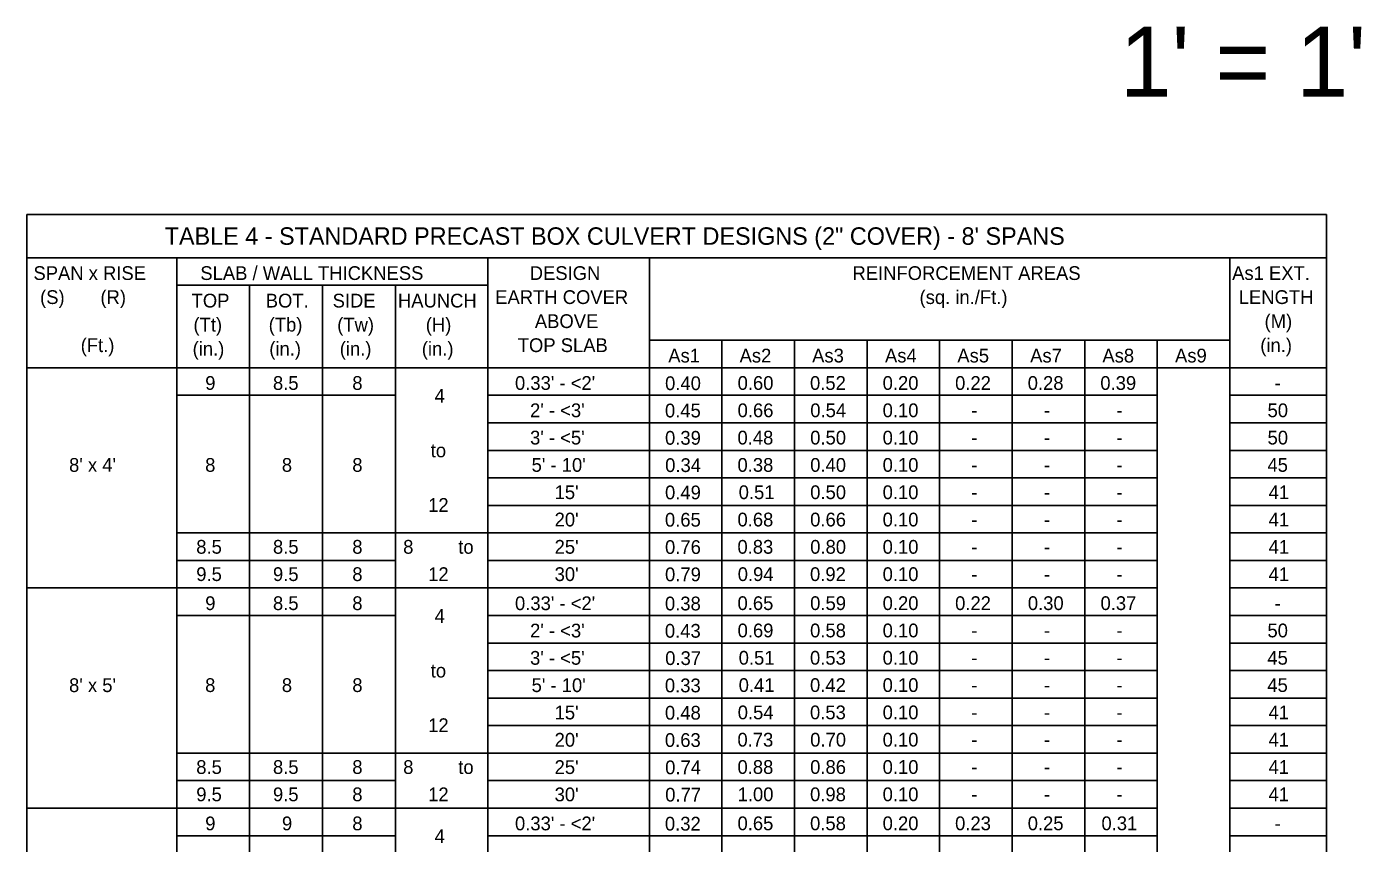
# Model space of a CAD drawing. Extents: x 10342.77 to 10344.98, y 76399.47 to 76400.59.
# Drawn here: x 10343.418 to 10344.028, y 76400.212 to 76400.586 of the extents above; entities that cross this region are included whole.
import ezdxf

# ---------------------------------------------------------------- set-up
doc = ezdxf.new("R2010")
doc.units = 0
doc.layers.add('AdhocPoint_dp', color=7, linetype='Continuous')
doc.layers.add('PlotBorder_dp', color=7, linetype='Continuous')

msp = doc.modelspace()

# ---------------------------------------------------------------- linework, layer by layer
at = {"layer": 'PlotBorder_dp'}
for p, q in [((10343.41763, 76400.49971), (10344.01237, 76400.49971)), ((10343.41763, 76400.49971), (10343.41763, 76399.92549)), ((10344.01237, 76400.49971), (10344.01237, 76399.92549)), ((10343.41763, 76400.47984), (10344.01237, 76400.47984)), ((10343.48627, 76400.47984), (10343.48627, 76399.92549)), ((10343.62871, 76400.47984), (10343.62871, 76399.92549)), ((10343.70259, 76400.47984), (10343.70259, 76399.92549)), ((10343.96818, 76400.47984), (10343.96818, 76399.92549)), ((10343.48627, 76400.46724), (10343.62871, 76400.46724)), ((10343.51963, 76400.46724), (10343.51963, 76399.92549)), ((10343.55299, 76400.46724), (10343.55299, 76399.92549)), ((10343.58635, 76400.46724), (10343.58635, 76399.92549)), ((10343.70259, 76400.44209), (10343.96818, 76400.44209)), ((10343.73579, 76400.44209), (10343.73579, 76399.92549)), ((10343.76899, 76400.44209), (10343.76899, 76399.92549)), ((10343.80219, 76400.44209), (10343.80219, 76399.92549)), ((10343.83539, 76400.44209), (10343.83539, 76399.92549)), ((10343.86859, 76400.44209), (10343.86859, 76399.92549)), ((10343.86859, 76400.44209), (10343.86859, 76399.92549)), ((10343.90178, 76400.44209), (10343.90178, 76399.92549)), ((10343.93498, 76400.44209), (10343.93498, 76399.92549)), ((10343.41763, 76400.42949), (10344.01237, 76400.42949)), ((10343.58635, 76400.41689), (10343.48627, 76400.41689)), ((10343.62871, 76400.41689), (10343.93498, 76400.41689)), ((10343.96818, 76400.41689), (10344.01237, 76400.41689)), ((10343.62871, 76400.40429), (10343.93498, 76400.40429)), ((10343.96818, 76400.40429), (10344.01237, 76400.40429)), ((10343.62871, 76400.39169), (10343.93498, 76400.39169)), ((10343.96818, 76400.39169), (10344.01237, 76400.39169)), ((10343.62871, 76400.37909), (10343.93498, 76400.37909)), ((10343.96818, 76400.37909), (10344.01237, 76400.37909)), ((10343.62871, 76400.36649), (10343.93498, 76400.36649)), ((10343.96818, 76400.36649), (10344.01237, 76400.36649)), ((10343.62871, 76400.35389), (10343.48627, 76400.35389)), ((10343.62871, 76400.35389), (10343.93498, 76400.35389)), ((10343.96818, 76400.35389), (10344.01237, 76400.35389)), ((10343.58635, 76400.34129), (10343.48627, 76400.34129)), ((10343.62871, 76400.34129), (10343.93498, 76400.34129)), ((10343.96818, 76400.34129), (10344.01237, 76400.34129)), ((10343.41763, 76400.32869), (10343.93498, 76400.32869)), ((10343.62931, 76400.32869), (10343.70148, 76400.32869)), ((10343.62931, 76400.32869), (10343.70148, 76400.32869)), ((10343.96818, 76400.32869), (10344.01237, 76400.32869)), ((10343.58635, 76400.31609), (10343.48627, 76400.31609)), ((10343.62871, 76400.31609), (10343.93498, 76400.31609)), ((10343.96818, 76400.31609), (10344.01237, 76400.31609)), ((10343.62871, 76400.30349), (10343.93498, 76400.30349)), ((10343.96818, 76400.30349), (10344.01237, 76400.30349)), ((10343.62871, 76400.29089), (10343.93498, 76400.29089)), ((10343.96818, 76400.29089), (10344.01237, 76400.29089)), ((10343.62871, 76400.27829), (10343.93498, 76400.27829)), ((10343.96818, 76400.27829), (10344.01237, 76400.27829)), ((10343.62871, 76400.26569), (10343.93498, 76400.26569)), ((10343.96818, 76400.26569), (10344.01237, 76400.26569)), ((10343.62871, 76400.25309), (10343.48627, 76400.25309)), ((10343.62871, 76400.25309), (10343.93498, 76400.25309)), ((10343.96818, 76400.25309), (10344.01237, 76400.25309)), ((10343.58635, 76400.24049), (10343.48627, 76400.24049)), ((10343.62871, 76400.24049), (10343.93498, 76400.24049)), ((10343.96818, 76400.24049), (10344.01237, 76400.24049)), ((10343.41763, 76400.22789), (10343.93498, 76400.22789)), ((10343.62931, 76400.22789), (10343.70148, 76400.22789)), ((10343.62931, 76400.22789), (10343.70148, 76400.22789)), ((10343.62931, 76400.22789), (10343.70148, 76400.22789)), ((10343.96818, 76400.22789), (10344.01237, 76400.22789)), ((10343.58635, 76400.21529), (10343.48627, 76400.21529)), ((10343.62871, 76400.21529), (10343.93498, 76400.21529)), ((10343.96818, 76400.21529), (10344.01237, 76400.21529))]:
    msp.add_line(p, q, dxfattribs=at)

# ---------------------------------------------------------------- texts
at = {"layer": 'AdhocPoint_dp'}
for s, height, p in [("1' = 1'", 0.032, (10343.91778, 76400.55363)), ('TABLE 4 - STANDARD PRECAST BOX CULVERT DESIGNS (2" COVER) - 8\' SPANS', 0.008, (10343.48078, 76400.48578)), ('SLAB / WALL THICKNESS', 0.0063, (10343.49709, 76400.46968)), ('As1', 0.0063, (10343.71121, 76400.43192)), ('As2', 0.0063, (10343.74384, 76400.43192)), ('As3', 0.0063, (10343.77704, 76400.43192)), ('As4', 0.0063, (10343.81037, 76400.43192)), ('As5', 0.0063, (10343.84347, 76400.43192)), ('As7', 0.0063, (10343.87681, 76400.43192)), ('As8', 0.0063, (10343.90985, 76400.43192)), ('As9', 0.0063, (10343.9431, 76400.43192))]:
    msp.add_text(s, height=height, dxfattribs=at).set_placement(p)
at = {"layer": 'PlotBorder_dp'}
for s, p in [('SPAN x RISE', (10343.42072, 76400.46968)), ('DESIGN', (10343.64781, 76400.46968)), ('REINFORCEMENT AREAS', (10343.79549, 76400.46968)), ('(S)       (R)', (10343.42376, 76400.45868)), ('EARTH COVER', (10343.63202, 76400.45868)), ('(sq. in./Ft.)', (10343.82619, 76400.45868)), ('TOP', (10343.49309, 76400.45708)), ('BOT.', (10343.52702, 76400.45708)), ('SIDE', (10343.55762, 76400.45708)), ('HAUNCH', (10343.58751, 76400.45708)), ('(Tt)', (10343.49394, 76400.44608)), ('(Tb)', (10343.52836, 76400.44608)), ('(Tw)', (10343.55972, 76400.44608)), ('(H)', (10343.60025, 76400.44608)), ('ABOVE', (10343.65016, 76400.44768)), ('(Ft.)', (10343.44234, 76400.43668)), ('(in.)', (10343.49355, 76400.43508)), ('(in.)', (10343.52864, 76400.43508)), ('(in.)', (10343.56088, 76400.43508)), ('(in.)', (10343.59844, 76400.43508)), ('TOP SLAB', (10343.64233, 76400.43668)), ('9', (10343.49933, 76400.41937)), ('8.5', (10343.53032, 76400.41937)), ('8', (10343.56662, 76400.41937)), ("0.33' - <2'", (10343.64107, 76400.41937)), ('0.40', (10343.70975, 76400.41927)), ('0.60', (10343.74294, 76400.41937)), ('0.52', (10343.77607, 76400.41937)), ('0.20', (10343.8093, 76400.41937)), ('0.22', (10343.84246, 76400.41937)), ('0.28', (10343.87568, 76400.41937)), ('0.39', (10343.90891, 76400.41937)), ('-', (10343.98869, 76400.41937)), ('4', (10343.60429, 76400.41352)), ("2' - <3'", (10343.64797, 76400.40687)), ('0.45', (10343.70969, 76400.40677)), ('0.66', (10343.74293, 76400.40687)), ('0.54', (10343.77619, 76400.40687)), ('0.10', (10343.8093, 76400.40687)), ('-', (10343.84986, 76400.40687)), ('-', (10343.88307, 76400.40687)), ('-', (10343.91625, 76400.40687)), ('50', (10343.98543, 76400.40687)), ("3' - <5'", (10343.64797, 76400.39437)), ('0.39', (10343.70973, 76400.39427)), ('0.48', (10343.74288, 76400.39437)), ('0.50', (10343.77615, 76400.39437)), ('0.10', (10343.8093, 76400.39437)), ('-', (10343.84986, 76400.39437)), ('-', (10343.88307, 76400.39437)), ('-', (10343.91625, 76400.39437)), ('50', (10343.98543, 76400.39437)), ('to', (10343.60251, 76400.38852)), ("8' x 4'", (10343.43702, 76400.38187)), ('8', (10343.49929, 76400.38187)), ('8', (10343.53438, 76400.38187)), ('8', (10343.56662, 76400.38187)), ("5' - 10'", (10343.64868, 76400.38187)), ('0.34', (10343.70979, 76400.38177)), ('0.38', (10343.74288, 76400.38187)), ('0.40', (10343.77615, 76400.38187)), ('0.10', (10343.8093, 76400.38187)), ('45', (10343.98538, 76400.38187)), ('-', (10343.84986, 76400.38187)), ('-', (10343.88307, 76400.38187)), ('-', (10343.91625, 76400.38187)), ("15'", (10343.6592, 76400.36937)), ('0.49', (10343.70973, 76400.36927)), ('0.51', (10343.74343, 76400.36937)), ('0.50', (10343.77615, 76400.36937)), ('0.10', (10343.8093, 76400.36937)), ('41', (10343.98592, 76400.36937)), ('12', (10343.60134, 76400.36352)), ('-', (10343.84986, 76400.36937)), ('-', (10343.88307, 76400.36937)), ('-', (10343.91625, 76400.36937)), ("20'", (10343.6592, 76400.35687)), ('0.65', (10343.70969, 76400.35677)), ('0.68', (10343.74288, 76400.35687)), ('0.66', (10343.77613, 76400.35687)), ('0.10', (10343.8093, 76400.35687)), ('41', (10343.98592, 76400.35687)), ('-', (10343.84986, 76400.35687)), ('-', (10343.88307, 76400.35687)), ('-', (10343.91625, 76400.35687)), ('8.5', (10343.49522, 76400.34437)), ('8.5', (10343.53032, 76400.34437)), ('8', (10343.56662, 76400.34437)), ('8 ', (10343.58991, 76400.34437)), ('to', (10343.61511, 76400.34437)), ("25'", (10343.6592, 76400.34437)), ('0.76', (10343.70973, 76400.34427)), ('0.83', (10343.74286, 76400.34437)), ('0.80', (10343.77615, 76400.34437)), ('0.10', (10343.8093, 76400.34437)), ('41', (10343.98592, 76400.34437)), ('-', (10343.84986, 76400.34437)), ('-', (10343.88307, 76400.34437)), ('-', (10343.91625, 76400.34437)), ('9.5', (10343.49522, 76400.33187)), ('9.5', (10343.53032, 76400.33187)), ('8', (10343.56662, 76400.33187)), ('12', (10343.60134, 76400.33187)), ("30'", (10343.6592, 76400.33187)), ('0.79', (10343.70973, 76400.33177)), ('0.94', (10343.74299, 76400.33187)), ('0.92', (10343.77607, 76400.33187)), ('0.10', (10343.8093, 76400.33187)), ('41', (10343.98592, 76400.33187)), ('-', (10343.84986, 76400.33187)), ('-', (10343.88307, 76400.33187)), ('-', (10343.91625, 76400.33187)), ('9', (10343.49933, 76400.31857)), ('8.5', (10343.53032, 76400.31857)), ('8', (10343.56662, 76400.31857)), ("0.33' - <2'", (10343.64107, 76400.31854)), ('0.38', (10343.70969, 76400.31843)), ('0.65', (10343.74289, 76400.31859)), ('0.59', (10343.77613, 76400.31859)), ('0.20', (10343.8093, 76400.31859)), ('0.22', (10343.84246, 76400.31859)), ('0.30', (10343.87574, 76400.31859)), ('0.37', (10343.90899, 76400.31859)), ('4', (10343.60429, 76400.31272)), ('-', (10343.98864, 76400.31859)), ("2' - <3'", (10343.64797, 76400.30604)), ('0.43', (10343.70966, 76400.30593)), ('0.69', (10343.74293, 76400.30609)), ('0.58', (10343.77609, 76400.30609)), ('0.10', (10343.8093, 76400.30609)), ('50', (10343.98538, 76400.30609)), ('-', (10343.84986, 76400.30609)), ('-', (10343.88307, 76400.30609)), ('-', (10343.91625, 76400.30609)), ("3' - <5'", (10343.64797, 76400.29354)), ('0.37', (10343.70981, 76400.29343)), ('0.51', (10343.74343, 76400.29359)), ('0.53', (10343.77606, 76400.29359)), ('0.10', (10343.8093, 76400.29359)), ('45', (10343.98533, 76400.29359)), ('to', (10343.60251, 76400.28772)), ('-', (10343.84986, 76400.29359)), ('-', (10343.88307, 76400.29359)), ('-', (10343.91625, 76400.29359)), ("8' x 5'", (10343.43702, 76400.28104)), ('8', (10343.49929, 76400.28107)), ('8', (10343.53438, 76400.28107)), ('8', (10343.56662, 76400.28107)), ("5' - 10'", (10343.64868, 76400.28104)), ('0.33', (10343.70966, 76400.28093)), ('0.41', (10343.74343, 76400.28109)), ('0.42', (10343.77607, 76400.28109)), ('0.10', (10343.8093, 76400.28109)), ('45', (10343.98533, 76400.28109)), ('-', (10343.84986, 76400.28109)), ('-', (10343.88307, 76400.28109)), ('-', (10343.91625, 76400.28109)), ('0.54', (10343.74299, 76400.26859)), ('0.53', (10343.77606, 76400.26859)), ('0.10', (10343.8093, 76400.26859)), ('12', (10343.60134, 76400.26272)), ("15'", (10343.6592, 76400.26854)), ('0.48', (10343.70969, 76400.26843)), ('-', (10343.84986, 76400.26859)), ('-', (10343.88307, 76400.26859)), ('-', (10343.91625, 76400.26859)), ('41', (10343.98587, 76400.26859)), ("20'", (10343.6592, 76400.25604)), ('0.63', (10343.70966, 76400.25593)), ('0.73', (10343.74286, 76400.25609)), ('0.70', (10343.77615, 76400.25609)), ('0.10', (10343.8093, 76400.25609)), ('-', (10343.84986, 76400.25609)), ('-', (10343.88307, 76400.25609)), ('-', (10343.91625, 76400.25609)), ('41', (10343.98587, 76400.25609)), ('8.5', (10343.49522, 76400.24357)), ('8.5', (10343.53032, 76400.24357)), ('8', (10343.56662, 76400.24357)), ('8 ', (10343.58991, 76400.24357)), ('to', (10343.61511, 76400.24357)), ("25'", (10343.6592, 76400.24354)), ('0.74', (10343.70979, 76400.24343)), ('0.88', (10343.74288, 76400.24359)), ('0.86', (10343.77613, 76400.24359)), ('0.10', (10343.8093, 76400.24359)), ('-', (10343.84986, 76400.24359)), ('-', (10343.88307, 76400.24359)), ('-', (10343.91625, 76400.24359)), ('41', (10343.98587, 76400.24359)), ('9.5', (10343.49522, 76400.23107)), ('9.5', (10343.53032, 76400.23107)), ('8', (10343.56662, 76400.23107)), ('12', (10343.60134, 76400.23107)), ("30'", (10343.6592, 76400.23104)), ('0.77', (10343.70981, 76400.23093)), ('1.00', (10343.74294, 76400.23109)), ('0.98', (10343.77609, 76400.23109)), ('0.10', (10343.8093, 76400.23109)), ('-', (10343.84986, 76400.23109)), ('-', (10343.88307, 76400.23109)), ('-', (10343.91625, 76400.23109)), ('41', (10343.98587, 76400.23109)), ('9', (10343.49933, 76400.21777)), ('9', (10343.53443, 76400.21777)), ('8', (10343.56662, 76400.21777)), ("0.33' - <2'", (10343.64107, 76400.21776)), ('0.32', (10343.70967, 76400.21765)), ('0.65', (10343.74289, 76400.21781)), ('0.58', (10343.77609, 76400.21781)), ('0.20', (10343.8093, 76400.21781)), ('0.23', (10343.84245, 76400.21781)), ('0.25', (10343.87569, 76400.21781)), ('0.31', (10343.90942, 76400.21781)), ('-', (10343.98864, 76400.21776)), ('4', (10343.60429, 76400.21192))]:
    msp.add_text(s, height=0.0063, dxfattribs=at).set_placement(p)
for s, p in [('As1 EXT.', (10343.96923, 76400.46968)), ('LENGTH', (10343.97225, 76400.45868)), ('(M)', (10343.98406, 76400.44768)), ('(in.)', (10343.9821, 76400.43668))]:
    msp.add_text(s, height=0.0063, rotation=360, dxfattribs=at).set_placement(p)

doc.saveas('drawing.dxf')
